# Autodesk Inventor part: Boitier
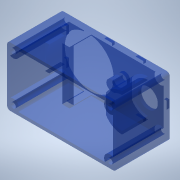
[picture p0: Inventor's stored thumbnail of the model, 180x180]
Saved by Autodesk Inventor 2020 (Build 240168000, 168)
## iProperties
Created: 2002-01
Part Number: Boitier
Project: Servo
Material: Générique
Document SubType Name: Modélisation
Designer: Philippe
Density: 1 g/cm^3
Appearance: Bleu (transparent)
Control State: 0
Master: False
Checked Out: False
Shininess: 20.0
Angle Display Precision: 2
Document Length Units: 11269
Document Angle Units: 11279
Document Time Units: 11290
Document Mass Units: 11283
Document Length Units Precision: 3
Document Angle Units Precision: 2
Density: 0.0
Volumn: 0.0
Area: 0.0
PropertySet Name: Model Information
Author: Philippe
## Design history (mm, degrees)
sketch "Esquisse1"
  geometry: L1 (0, 0)-(21, 0); L2 (21, 0)-(21, 10.3); L3 (21, 10.3)-(0, 10.3); L4 (0, 10.3)-(0, 0)
  constraints: 8 end point, 2 parallel, 1 horizontal, 1 perpendicular, 1 other
  dimensions: "d0" = 21 distance of L1.start L1.end; "d1" = 10.3 distance of L3.end L1.start
extrude "Extrusion1" new body sketch "Esquisse1" stored distance "d2" = 11.4; taper "d3" = 0 deg
fillet "Congé1" dims "d4" = 0.6
feature "Coque1" dims "d5" = 0.6
sketch "Esquisse3"
  geometry: L1 (0, -11.4)-(19.8, -11.4) reference; L2 (20.4, -0.6)-(20.4, -10.8) reference; 1 further point
  dimensions: "d8" = 3.6 distance from line of L2 point (16.8, -5.7); "d9" = 5.7 distance from line of L1 point (16.8, -5.7) (= 0.5 x d2)
hole "Perçage1" sketch "Esquisse3" at (16.8, -5.7) diameter "d10" = 3.8; stored, may be unused: countersink angle "d14" = 82 deg, drill point angle "d16" = 118 deg; dims "d11" = 6, "d12" = 4, "d13" = 2, "d15" = 8
sketch "Esquisse4"
  geometry: L1 (0, 0)-(19.8, 0) reference; L2 (0, -10.2)-(0, 0) reference; L3 (19.8, -10.2)-(0, -10.2) reference; L4 (4.5, -10.2)-(5.9, -10.2); L5 (5.9, -10.2)-(5.9, 0); L6 (5.9, 0)-(4.5, 0); L7 (4.5, 0)-(4.5, -10.2); L8 (19.8, -10.2)-(19.8, 0) reference; L9 (4.5, -2.7)-(0, -2.7); L10 (4.5, -7.5)-(0, -7.5); L11 (19.8, 0.6)-(0, 0.6) reference
  constraints: 12 end point, 6 point on line, 3 perpendicular, 2 parallel, 1 horizontal
  dimensions: "d17" = 1.4 distance between parallel lines of L5 L7; "d18" = 4.5 distance between parallel lines of L7 L2; "d44" = 4.8 distance between parallel lines of L10 L9; "d45" = 3.3 distance between parallel lines of L11 L9 (= -0.5 x d44 + 0.5 x d2)
extrude "Extrusion3" join sketch "Esquisse4" distance "d19" = 4.2; taper "d20" = 0 deg
extrude "Extrusion6" join sketch "Esquisse4" distance "d46" = 3; taper "d47" = 0 deg
sketch "Esquisse6"
  geometry: L1 (20.4, -0.6)-(20.4, -10.8) reference; L2 (16.8, -5.7)-(5.2, -5.7); C1 r 1.9 at (16.8, -5.7) reference
  constraints: 2 end point, 1 perpendicular
  dimensions: "d22" = 11.6 distance of L2.start L2.end
hole "Perçage2" sketch "Esquisse6" at (5.2, -5.7) diameter "d23" = 10; stored, may be unused: countersink angle "d27" = 82 deg, drill point angle "d29" = 0 deg; dims "d24" = 6, "d25" = 4, "d26" = 2, "d28" = 4
sketch "Esquisse7"
  geometry: C1 r 1.9 at (16.8, -5.7) reference; C2 r 1 at (11.2, -5.7); C3 r 0.5 at (11.2, -5.7)
  constraints: 2 centre point, 1 coincident
  dimensions: "d30" = 5.6 distance of C1.centre C3.centre; "d31" = 1 diameter of C3; "d32" = 2 diameter of C2
extrude "Extrusion4" join sketch "Esquisse7" distance "d33" = 0.6; taper "d34" = 0 deg
sketch "Esquisse8"
  geometry: L1 (19.8, 0)-(0, 0) reference; L2 (20.4, -0.6)-(20.4, -10.8) reference; L3 (19.8, -0.6)-(0, -0.6) reference; L4 (7.8, -0.6)-(9.3, -0.6); L5 (9.3, -0.6)-(9.3, -1.1); L6 (9.3, -1.1)-(7.8, -1.1); L7 (7.8, -1.1)-(7.8, -0.6); L8 (13.8, -0.6)-(15.3, -0.6); L9 (15.3, -0.6)-(15.3, -1.1); L10 (15.3, -1.1)-(13.8, -1.1); L11 (13.8, -1.1)-(13.8, -0.6); L12 (19.8, -10.8)-(19.8, -0.6) reference; L13 (19.8, -4.95)-(19.3, -4.95); L14 (19.3, -4.95)-(19.3, -6.45); L15 (19.3, -6.45)-(19.8, -6.45); L16 (19.8, -6.45)-(19.8, -4.95); L17 (15.3, -10.8)-(13.8, -10.8); L18 (13.8, -10.8)-(13.8, -10.3); L19 (13.8, -10.3)-(15.3, -10.3); L20 (15.3, -10.3)-(15.3, -10.8); L21 (9.3, -10.8)-(7.8, -10.8); L22 (7.8, -10.8)-(7.8, -10.3); L23 (7.8, -10.3)-(9.3, -10.3); L24 (9.3, -10.3)-(9.3, -10.8); L25 (0, -0.6)-(0, -10.8) reference; L26 (0, -2.2)-(0.5, -2.2); L27 (0.5, -2.2)-(0.5, -3.7); L28 (0.5, -3.7)-(0, -3.7); L29 (0, -3.7)-(0, -2.2); L30 (0, -7.7)-(0.5, -7.7); L31 (0.5, -7.7)-(0.5, -9.2); L32 (0.5, -9.2)-(0, -9.2); L33 (0, -9.2)-(0, -7.7); L34 (5.9, -10.8)-(19.8, -10.8) reference; 1 further point
  constraints: 56 end point, 14 parallel, 12 equal length, 7 horizontal, 7 perpendicular, 5 point on line, 4 collinear
  dimensions: "d35" = 0.5 distance of L26.start L26.end; "d36" = 1.5 distance of L26.end L27.end; "d37" = 7.5 distance between parallel lines of L9 L7; "d38" = 7 distance between parallel lines of L32 L26; "d39" = 4.95 distance between parallel lines of L13 L1; "d40" = 2.2 distance between parallel lines of L26 L1; "d41" = 6.6 distance between parallel lines of L2 L18
extrude "Extrusion5" join sketch "Esquisse8" distance "d42" = 0.5; taper "d43" = 0 deg
sketch "Esquisse9"
  geometry: L1 (-0.6, -0.6)-(-0.6, -10.8) reference; L2 (0, -11.4)-(19.8, -11.4) reference; L3 (13.8, -10.8)-(13.8, -10.3) reference; L4 (13.8, -10.3)-(15.3, -10.3) reference; L5 (15.3, -10.3)-(15.3, -10.8) reference; L6 (15.3, -10.8)-(13.8, -10.8) reference; L7 (13.8, -0.6)-(15.3, -0.6) reference; L8 (15.3, -0.6)-(15.3, -1.1) reference; L9 (15.3, -1.1)-(13.8, -1.1) reference; L10 (13.8, -1.1)-(13.8, -0.6) reference; L11 (0, -2.2)-(0.5, -2.2) reference; L12 (0.5, -2.2)-(0.5, -3.7) reference; L13 (0.5, -3.7)-(0, -3.7) reference; L14 (0, -3.7)-(0, -2.2) reference; L15 (7.8, -0.6)-(9.3, -0.6) reference; L16 (9.3, -0.6)-(9.3, -1.1) reference; L17 (9.3, -1.1)-(7.8, -1.1) reference; L18 (7.8, -1.1)-(7.8, -0.6) reference; L19 (0, -7.7)-(0.5, -7.7) reference; L20 (0.5, -7.7)-(0.5, -9.2) reference; L21 (0.5, -9.2)-(0, -9.2) reference; L22 (0, -9.2)-(0, -7.7) reference; L23 (19.8, -4.95)-(19.8, -6.45) reference; L24 (19.8, -6.45)-(19.3, -6.45) reference; L25 (19.3, -6.45)-(19.3, -4.95) reference; L26 (19.3, -4.95)-(19.8, -4.95) reference; L27 (7.8, -10.8)-(7.8, -10.3) reference; L28 (7.8, -10.3)-(9.3, -10.3) reference; L29 (9.3, -10.3)-(9.3, -10.8) reference; L30 (9.3, -10.8)-(7.8, -10.8) reference; L31 (19.8, 0)-(0, 0) reference; L32 (20.4, -0.6)-(20.4, -10.8) reference; C1 r 1.15 at (0.6, -10.2); C2 r 1.15 at (0.6, -1.2); C3 r 1.15 at (19.2, -1.2); C4 r 1.15 at (19.2, -10.2); C5 r 0.5 at (0.6, -10.2); C6 r 0.5 at (0.6, -1.2); C7 r 0.5 at (19.2, -1.2); C8 r 0.5 at (19.2, -10.2); C9 r 1.9 at (16.8, -5.7) reference; C10 r 5 at (5.2, -5.7) reference; C11 r 1 at (11.2, -5.7) reference; A1 r 0.6 centre (19.8, -0.6) between (20.4, -0.6) and (19.8, 0) reference; A2 r 0.6 centre (0, -0.6) between (0, 0) and (-0.6, -0.6) reference; A3 r 0.6 centre (0, -10.8) between (-0.6, -10.8) and (0, -11.4) reference; A4 r 0.6 centre (19.8, -10.8) between (19.8, -11.4) and (20.4, -10.8) reference; 1 further point
  constraints: 8 centre point, 6 equal radius, 4 coincident, 2 horizontal alignment, 2 vertical alignment
  dimensions: "d48" = 9 distance of C1.centre C2.centre; "d49" = 1.2 distance from line of C1.centre L2 (= -0.5 x d48 + 0.5 x d2); "d50" = 18.6 distance of C4.centre C1.centre; "d51" = 1.2 distance from line of C2.centre L1; "d52" = 2.3 diameter of C1; "d53" = 1 diameter of C6
extrude "Extrusion7" join sketch "Esquisse9" distance "d54" = 10.3 (= d1); taper "d55" = 0 deg
extrude "Extrusion8" cut sketch "Esquisse9" extent not by distance; stored distance "d56" = 10.3 (= d1); taper "d57" = 0 deg
sketch "Esquisse11"
  geometry: L1 (13.019, -5.1)-(0.7, -5.1) reference; L2 (11.6, 3)-(11.6, 3.6); L3 (8.5, 1.83)-(8.5, -1.83); L4 (11.6, -3)-(11.6, -3.6); L5 (9.1, 1.658)-(9.1, -1.658); C1 r 1.9 at (11.6, 0) reference; A1 r 3.6 centre (11.6, 0) between (11.6, 3.6) and (8.5, 1.83); A2 r 3.6 centre (11.6, 0) between (8.5, -1.83) and (11.6, -3.6); A3 r 3 centre (11.6, 0) between (11.6, 3) and (9.1, 1.658); A4 r 3 centre (11.6, 0) between (9.1, -1.658) and (11.6, -3)
  constraints: 8 end point, 8 point on circle, 4 centre point, 2 parallel, 1 coincident, 1 collinear, 1 perpendicular
  dimensions: "d58" = 0.6 distance of L2.start L2.end; "d59" = 0.6 distance of L4.start L4.end; "d61" = 0.6 distance between parallel lines of L3 L5; "d62" = 3 radius of A3; "d63" = 3 radius of A4; "d64" = 2.5 distance from line of L5 C1.centre; "d65" = 3.6 radius of A2; "d66" = 3.6 radius of A1
extrude "Extrusion9" join sketch "Esquisse11" distance "d67" = 5; taper "d68" = 0 deg
extrude "Extrusion10" join sketch "Esquisse7" distance "d69" = 2; taper "d70" = 0 deg
extrude "Extrusion11" cut sketch "Esquisse7" distance "d71" = 1.4; taper "d72" = 0 deg
node "Solide1"
node "Corps solides"
node "Corps surfaciques"
